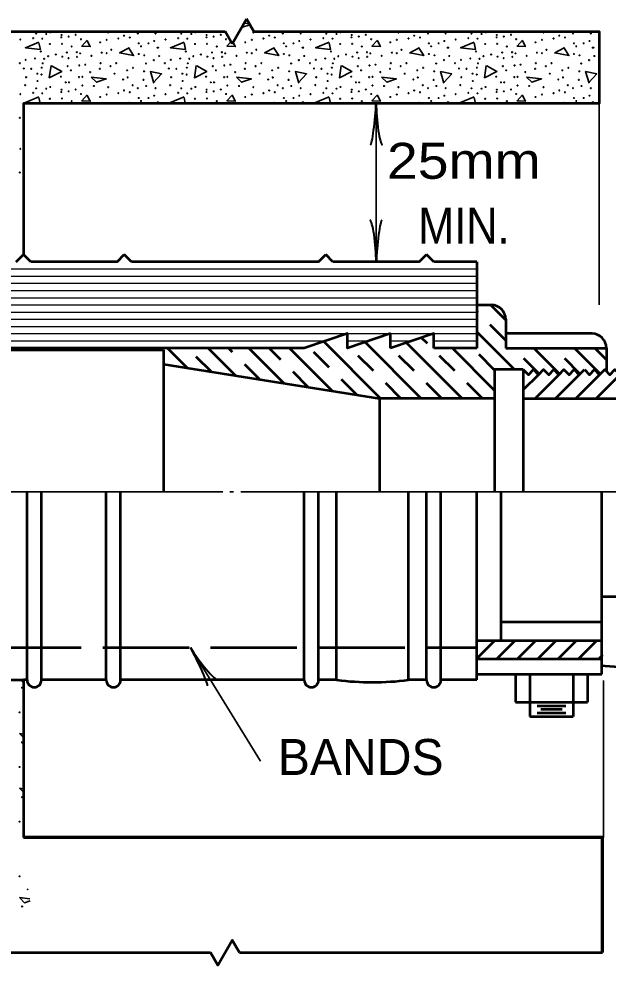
# Model space of a CAD drawing. Extents: x -50 to 806, y -9 to 535.
# Drawn here: x 191.8 to 241, y 352.2 to 431.1 of the extents above; entities that cross this region are included whole.
import ezdxf
from ezdxf.enums import TextEntityAlignment as Align

# ---------------------------------------------------------------- set-up
doc = ezdxf.new("R2010")
doc.units = 0
doc.header["$LTSCALE"] = 1.2
doc.linetypes.add('LONG_DASHED', pattern=[7.5, 6, -1.5])
doc.linetypes.add('SHORT_DASHED', pattern=[2.7, 1.5, -1.2])
doc.layers.add('1', color=7, linetype='Continuous', lineweight=35)

msp = doc.modelspace()

# ---------------------------------------------------------------- linework, layer by layer
at = {"layer": '1', "lineweight": 53}
for p, q in [((209.621, 429.012), (210.821, 431.09)), ((211.421, 430.051), (210.821, 431.09)), ((183.821, 430.051), (209.021, 430.051)), ((209.621, 429.012), (209.021, 430.051)), ((191.621, 410.851), (192.221, 411.451)), ((192.821, 410.851), (192.221, 411.451)), ((200.021, 410.851), (200.621, 411.451)), ((201.221, 410.851), (200.621, 411.451)), ((216.821, 410.851), (217.421, 411.451)), ((218.021, 410.851), (217.421, 411.451)), ((225.221, 410.851), (225.821, 411.451)), ((226.421, 410.851), (225.821, 411.451)), ((200.021, 410.851), (192.821, 410.851)), ((216.821, 410.851), (201.221, 410.851)), ((225.221, 410.851), (218.021, 410.851)), ((230.021, 410.851), (226.421, 410.851)), ((230.021, 410.851), (230.021, 403.651)), ((230.021, 407.251), (231.221, 407.251)), ((232.408, 406.004), (231.164, 407.248)), ((232.421, 406.051), (232.421, 403.651)), ((222.821, 403.651), (222.821, 404.851)), ((233.17, 401.848), (230.008, 405.01)), ((239.621, 404.851), (232.421, 404.851)), ((221.994, 399.448), (217.247, 404.194)), ((225.388, 399.448), (220.693, 404.143)), ((228.782, 399.448), (224.138, 404.091)), ((215.621, 403.651), (177.221, 403.651)), ((188.956, 403.501), (203.887, 403.501)), ((203.887, 403.501), (203.887, 391.651)), ((205.886, 401.979), (204.217, 403.648)), ((209.919, 401.341), (207.611, 403.648)), ((213.951, 400.702), (211.006, 403.648)), ((217.984, 400.064), (214.4, 403.648)), ((230.021, 403.651), (226.421, 403.651)), ((231.473, 400.151), (227.976, 403.648)), ((232.421, 403.651), (240.821, 403.651)), ((236.916, 401.496), (234.764, 403.648)), ((240.31, 401.496), (238.158, 403.648)), ((240.821, 403.651), (240.821, 401.705)), ((203.887, 402.301), (221.887, 399.451)), ((233.887, 401.851), (231.487, 401.851)), ((231.487, 401.851), (231.487, 391.651)), ((233.887, 401.851), (233.887, 391.651)), ((238.554, 401.427), (238.978, 401.851)), ((235.15, 401.418), (233.889, 400.157)), ((236.847, 401.418), (234.859, 399.43)), ((238.544, 401.418), (236.556, 399.43)), ((240.241, 401.418), (238.253, 399.43)), ((241.938, 401.418), (239.95, 399.43)), ((231.487, 399.451), (221.887, 399.451)), ((221.887, 399.451), (221.887, 391.651)), ((233.887, 399.451), (269.887, 399.451)), ((192.521, 375.979), (192.521, 391.651)), ((193.721, 375.979), (193.721, 391.651)), ((199.121, 375.979), (199.121, 391.651)), ((200.321, 375.979), (200.321, 391.651)), ((215.621, 375.979), (215.621, 391.651)), ((216.821, 375.979), (216.821, 391.651)), ((218.321, 375.979), (218.321, 391.651)), ((224.321, 375.979), (224.321, 391.651)), ((225.821, 375.979), (225.821, 391.651)), ((227.021, 375.979), (227.021, 391.651)), ((230.021, 375.979), (230.021, 391.651)), ((232.043, 379.241), (232.043, 391.651)), ((240.443, 379.592), (240.443, 391.651)), ((240.521, 382.951), (267.521, 382.951)), ((240.443, 380.803), (232.043, 380.803)), ((240.443, 376.478), (240.443, 379.592)), ((229.999, 377.741), (231.499, 379.241)), ((240.521, 379.241), (230.021, 379.241)), ((231.696, 377.741), (233.196, 379.241)), ((233.393, 377.741), (234.893, 379.241)), ((235.09, 377.741), (236.59, 379.241)), ((236.787, 377.741), (238.287, 379.241)), ((238.485, 377.741), (239.985, 379.241)), ((240.181, 377.741), (240.521, 378.081)), ((230.021, 377.741), (240.521, 377.741)), ((230.021, 376.478), (240.443, 376.478)), ((233.243, 376.533), (233.243, 374.133)), ((234.443, 376.533), (234.443, 372.933)), ((238.043, 376.533), (238.043, 372.933)), ((239.243, 376.533), (239.243, 374.133)), ((192.521, 375.979), (192.221, 375.979)), ((199.121, 375.979), (193.721, 375.979)), ((215.621, 375.979), (200.321, 375.979)), ((218.321, 375.979), (216.821, 375.979)), ((225.821, 375.979), (224.321, 375.979)), ((230.021, 375.979), (227.021, 375.979)), ((233.243, 374.133), (239.243, 374.133)), ((235.043, 373.833), (237.443, 373.833)), ((235.043, 373.233), (237.443, 373.233)), ((235.343, 373.533), (237.143, 373.533)), ((234.443, 372.933), (238.043, 372.933)), ((168.221, 353.251), (207.821, 353.251)), ((210.221, 353.251), (240.491, 353.251))]:
    msp.add_line(p, q, dxfattribs=at)
at = {"layer": '1'}
for p, q in [((210.609, 430.724), (211.063, 430.672)), ((193.612, 424.051), (193.507, 424.534)), ((205.708, 424.051), (205.603, 424.534)), ((217.804, 424.051), (217.699, 424.534)), ((229.9, 424.051), (229.795, 424.534)), ((201.019, 424.126), (200.882, 424.051)), ((201.034, 424.051), (200.971, 424.15)), ((213.115, 424.126), (212.978, 424.051)), ((213.13, 424.051), (213.067, 424.15)), ((221.621, 410.851), (221.621, 424.051)), ((225.211, 424.126), (225.074, 424.051)), ((225.226, 424.051), (225.163, 424.15)), ((237.307, 424.126), (237.17, 424.051)), ((237.322, 424.051), (237.259, 424.15)), ((240.221, 424.051), (240.221, 407.251)), ((170.506, 391.651), (208.831, 391.651)), ((209.431, 391.651), (209.731, 391.651)), ((210.331, 391.651), (218.321, 391.651)), ((206.139, 378.679), (211.986, 369.209)), ((192.221, 375.738), (191.98, 375.979)), ((240.569, 362.851), (240.569, 375.932)), ((191.885, 371.515), (192.221, 371.476)), ((192.221, 371.178), (191.885, 371.515)), ((191.885, 366.955), (192.221, 366.916)), ((192.221, 366.618), (191.885, 366.955)), ((191.885, 357.835), (192.752, 357.735))]:
    msp.add_line(p, q, dxfattribs=at)
at = {"layer": '1', "lineweight": 25}
for p, q in [((162.821, 410.251), (230.021, 410.251)), ((162.821, 409.651), (230.021, 409.651)), ((162.821, 409.051), (230.021, 409.051)), ((162.821, 408.451), (230.021, 408.451)), ((162.821, 407.851), (230.021, 407.851)), ((162.821, 407.251), (230.021, 407.251)), ((162.821, 406.651), (230.021, 406.651)), ((162.821, 406.051), (230.021, 406.051)), ((162.821, 405.451), (230.021, 405.451)), ((162.821, 404.851), (230.021, 404.851)), ((175.421, 404.251), (217.421, 404.251)), ((219.221, 404.251), (221.021, 404.251)), ((222.821, 404.251), (224.621, 404.251)), ((226.421, 404.251), (230.021, 404.251))]:
    msp.add_line(p, q, dxfattribs=at)
at = {"layer": '1', "linetype": 'SHORT_DASHED', "lineweight": 53}
for p, q in [((232.408, 404.307), (230.008, 406.707)), ((230.479, 399.448), (225.411, 404.516)), ((207.902, 401.66), (205.914, 403.648)), ((211.935, 401.021), (209.308, 403.648)), ((215.967, 400.383), (212.703, 403.648)), ((220, 399.744), (215.974, 403.77)), ((223.691, 399.448), (219.42, 403.719)), ((227.085, 399.448), (222.865, 403.667)), ((231.473, 401.848), (229.673, 403.648)), ((235.219, 401.496), (233.067, 403.648)), ((238.613, 401.496), (236.461, 403.648)), ((240.808, 402.695), (239.855, 403.648))]:
    msp.add_line(p, q, dxfattribs=at)
at = {"layer": '1', "linetype": 'LONG_DASHED', "lineweight": 53}
msp.add_line((162.821, 378.679), (230.021, 378.679), dxfattribs=at)
at = {"layer": '1', "lineweight": 70}
for p, q in [((240.491, 362.851), (192.221, 362.851)), ((240.491, 353.251), (240.491, 362.851))]:
    msp.add_line(p, q, dxfattribs=at)
at = {"layer": '1', "lineweight": 53}
for points in [[(211.421, 430.051), (240.221, 430.051), (240.221, 424.051), (192.221, 424.051), (192.221, 411.451)], [(222.821, 404.851), (219.221, 403.651), (219.221, 404.851), (215.621, 403.651)], [(226.421, 403.651), (226.421, 404.851), (222.821, 403.651)], [(233.887, 401.851), (234.311, 401.427), (234.735, 401.851), (235.159, 401.427), (235.584, 401.851), (236.008, 401.427), (236.432, 401.851), (236.857, 401.427), (237.281, 401.851), (237.705, 401.427), (238.13, 401.851), (238.554, 401.427)], [(238.978, 401.851), (239.402, 401.427), (239.827, 401.851), (240.251, 401.427), (240.675, 401.851), (241.1, 401.427), (241.524, 401.851), (241.948, 401.427), (242.373, 401.851), (242.797, 401.427), (243.221, 401.851)], [(179.064, 375.979), (192.221, 375.979), (192.221, 362.851)], [(207.821, 353.251), (208.421, 352.212), (209.621, 354.29), (210.221, 353.251)]]:
    msp.add_lwpolyline(points, dxfattribs=at)
at = {"layer": '1'}
for points in [[(211.098, 430.611), (210.403, 430.365), (210.403, 430.366)], [(193.507, 429.142), (192.379, 428.686), (193.627, 428.542), (193.507, 429.094)], [(197.539, 429.31), (197.083, 428.829), (197.779, 428.781), (197.539, 429.262)], [(205.603, 429.142), (204.475, 428.686), (205.723, 428.542), (205.603, 429.094)], [(209.519, 429.188), (209.179, 428.829), (209.875, 428.781), (209.695, 429.14)], [(217.699, 429.142), (216.571, 428.686), (217.819, 428.542), (217.699, 429.094)], [(221.731, 429.31), (221.275, 428.829), (221.971, 428.781), (221.731, 429.262)], [(229.795, 429.142), (228.667, 428.686), (229.915, 428.542), (229.795, 429.094)], [(233.827, 429.31), (233.371, 428.829), (234.067, 428.781), (233.827, 429.262)], [(201.019, 428.686), (200.227, 428.254), (201.403, 428.038), (200.971, 428.71)], [(213.115, 428.686), (212.323, 428.254), (213.499, 428.038), (213.067, 428.71)], [(225.211, 428.686), (224.419, 428.254), (225.595, 428.038), (225.163, 428.71)], [(237.307, 428.686), (236.515, 428.254), (237.691, 428.038), (237.259, 428.71)], [(194.563, 427.174), (195.403, 426.694), (194.371, 426.19), (194.515, 427.198)], [(206.659, 427.174), (207.499, 426.694), (206.467, 426.19), (206.611, 427.198)], [(218.755, 427.174), (219.595, 426.694), (218.563, 426.19), (218.707, 427.198)], [(230.851, 427.174), (231.691, 426.694), (230.659, 426.19), (230.803, 427.198)], [(203.083, 425.733), (202.795, 426.694), (203.731, 426.502), (203.059, 425.781)], [(215.179, 425.733), (214.891, 426.694), (215.827, 426.502), (215.155, 425.781)], [(227.275, 425.733), (226.987, 426.694), (227.923, 426.502), (227.251, 425.781)], [(239.371, 425.733), (239.083, 426.694), (240.019, 426.502), (239.347, 425.781)], [(193.507, 424.582), (192.379, 424.126), (193.025, 424.051)], [(197.539, 424.75), (197.083, 424.269), (197.779, 424.222), (197.539, 424.702)], [(205.603, 424.582), (204.475, 424.126), (205.121, 424.051)], [(209.635, 424.75), (209.179, 424.269), (209.875, 424.222), (209.635, 424.702)], [(217.699, 424.582), (216.571, 424.126), (217.216, 424.051)], [(221.731, 424.75), (221.275, 424.269), (221.971, 424.222), (221.731, 424.702)], [(229.795, 424.582), (228.667, 424.126), (229.312, 424.051)], [(233.827, 424.75), (233.371, 424.269), (234.067, 424.222), (233.827, 424.702)], [(218.321, 391.651), (233.887, 391.651), (240.521, 391.651), (250.121, 391.651)], [(192.769, 357.562), (192.317, 357.403), (191.885, 357.835)]]:
    msp.add_lwpolyline(points, dxfattribs=at)
for points in [[(197.875, 426.238), (199.123, 426.094), (198.307, 425.805)], [(209.971, 426.238), (211.219, 426.094), (210.403, 425.805)], [(222.067, 426.238), (223.315, 426.094), (222.499, 425.805)], [(234.163, 426.238), (235.411, 426.094), (234.595, 425.805)]]:
    msp.add_lwpolyline(points, close=True, dxfattribs=at)
for centre in [(193.279, 429.866), (194.456, 429.977), (199.284, 429.961), (201.749, 429.881), (203.228, 429.881), (205.375, 429.866), (206.552, 429.977), (211.38, 429.961), (213.845, 429.881), (215.324, 429.881), (217.471, 429.866), (218.648, 429.977), (223.476, 429.961), (225.941, 429.881), (227.42, 429.881), (229.567, 429.866), (230.744, 429.977), (235.572, 429.961), (238.037, 429.881), (239.516, 429.881), (191.959, 429.378), (193.024, 429.49), (193.788, 429.442), (194.122, 429.834), (195.378, 429.553), (195.394, 429.754), (195.982, 429.617), (196.571, 429.77), (197.01, 429.394), (198.616, 429.14), (199.157, 429.346), (200.127, 429.458), (200.604, 429.691), (201.081, 429.537), (203.117, 429.251), (204.055, 429.378), (205.12, 429.49), (205.884, 429.442), (206.218, 429.834), (207.474, 429.553), (207.49, 429.754), (208.078, 429.617), (208.667, 429.77), (209.106, 429.394), (210.712, 429.14), (211.253, 429.346), (212.223, 429.458), (212.7, 429.691), (213.177, 429.537), (215.213, 429.251), (216.151, 429.378), (217.216, 429.49), (217.98, 429.442), (218.314, 429.834), (219.57, 429.553), (219.586, 429.754), (220.174, 429.617), (220.763, 429.77), (221.202, 429.394), (222.808, 429.14), (223.349, 429.346), (224.319, 429.458), (224.796, 429.691), (225.273, 429.537), (227.309, 429.251), (228.247, 429.378), (229.312, 429.49), (230.076, 429.442), (230.41, 429.834), (231.666, 429.553), (231.682, 429.754), (232.27, 429.617), (232.859, 429.77), (233.298, 429.394), (234.904, 429.14), (235.445, 429.346), (236.415, 429.458), (236.892, 429.691), (237.369, 429.537), (239.405, 429.251), (193.661, 428.376), (194.424, 428.996), (195.426, 429.012), (195.839, 428.296), (196.237, 428.79), (196.666, 428.312), (198.743, 428.28), (199.538, 428.519), (201.828, 429.06), (202.019, 428.805), (202.639, 429.06), (203.387, 428.694), (203.451, 428.694), (205.757, 428.376), (206.52, 428.996), (207.522, 429.012), (207.935, 428.296), (208.333, 428.79), (208.762, 428.312), (210.839, 428.28), (211.634, 428.519), (213.924, 429.06), (214.115, 428.805), (214.735, 429.06), (215.483, 428.694), (215.547, 428.694), (217.853, 428.376), (218.616, 428.996), (219.618, 429.012), (220.031, 428.296), (220.429, 428.79), (220.858, 428.312), (222.935, 428.28), (223.73, 428.519), (226.02, 429.06), (226.211, 428.805), (226.831, 429.06), (227.579, 428.694), (227.643, 428.694), (229.949, 428.376), (230.712, 428.996), (231.714, 429.012), (232.127, 428.296), (232.525, 428.79), (232.954, 428.312), (235.031, 428.28), (235.826, 428.519), (238.116, 429.06), (238.307, 428.805), (238.927, 429.06), (239.675, 428.694), (239.739, 428.694), (192.404, 427.676), (193.183, 427.787), (193.947, 427.771), (194.281, 427.978), (194.917, 428.121), (195.458, 427.946), (195.967, 427.819), (196.682, 427.93), (196.946, 428.217), (197.884, 428.01), (199.157, 428.233), (201.828, 428.169), (202.29, 428.058), (203.085, 427.66), (203.53, 427.994), (204.5, 427.676), (205.279, 427.787), (206.043, 427.771), (206.377, 427.978), (207.013, 428.121), (207.554, 427.946), (208.063, 427.819), (208.778, 427.93), (209.042, 428.217), (209.98, 428.01), (211.253, 428.233), (213.924, 428.169), (214.386, 428.058), (215.181, 427.66), (215.626, 427.994), (216.596, 427.676), (217.375, 427.787), (218.139, 427.771), (218.473, 427.978), (219.109, 428.121), (219.65, 427.946), (220.159, 427.819), (220.874, 427.93), (221.138, 428.217), (222.076, 428.01), (223.349, 428.233), (226.02, 428.169), (226.482, 428.058), (227.277, 427.66), (227.722, 427.994), (228.692, 427.676), (229.471, 427.787), (230.235, 427.771), (230.569, 427.978), (231.205, 428.121), (231.746, 427.946), (232.255, 427.819), (232.97, 427.93), (233.234, 428.217), (234.172, 428.01), (235.445, 428.233), (238.116, 428.169), (238.578, 428.058), (239.373, 427.66), (239.818, 427.994), (191.911, 427.405), (192.245, 426.96), (192.865, 426.928), (193.74, 427.024), (193.82, 427.39), (195.903, 427.151), (196.173, 426.801), (196.873, 427.215), (197.375, 427.278), (198.584, 426.928), (198.648, 427.405), (199.475, 427.151), (199.952, 427.405), (200.858, 426.801), (201.351, 427.008), (202.274, 426.721), (202.433, 427.374), (204.007, 427.405), (204.341, 426.96), (204.961, 426.928), (205.836, 427.024), (205.916, 427.39), (207.999, 427.151), (208.269, 426.801), (208.969, 427.215), (209.471, 427.278), (210.68, 426.928), (210.744, 427.405), (211.571, 427.151), (212.048, 427.405), (212.954, 426.801), (213.447, 427.008), (214.37, 426.721), (214.529, 427.374), (216.103, 427.405), (216.437, 426.96), (217.057, 426.928), (217.932, 427.024), (218.012, 427.39), (220.095, 427.151), (220.365, 426.801), (221.065, 427.215), (221.567, 427.278), (222.776, 426.928), (222.84, 427.405), (223.667, 427.151), (224.144, 427.405), (225.05, 426.801), (225.543, 427.008), (226.466, 426.721), (226.625, 427.374), (228.199, 427.405), (228.533, 426.96), (229.153, 426.928), (230.028, 427.024), (230.108, 427.39), (232.191, 427.151), (232.461, 426.801), (233.161, 427.215), (233.663, 427.278), (234.872, 426.928), (234.936, 427.405), (235.763, 427.151), (236.24, 427.405), (237.146, 426.801), (237.639, 427.008), (238.562, 426.721), (238.721, 427.374), (192.436, 426.228), (193.374, 426.53), (193.39, 425.91), (193.724, 426.451), (195.346, 426.276), (196.849, 426.241), (197.121, 426.26), (197.773, 426.658), (199.809, 426.53), (200.524, 426.037), (200.906, 426.212), (202.226, 426.005), (204.532, 426.228), (205.47, 426.53), (205.486, 425.91), (205.82, 426.451), (207.442, 426.276), (208.945, 426.241), (209.217, 426.26), (209.869, 426.658), (211.905, 426.53), (212.62, 426.037), (213.002, 426.212), (214.322, 426.005), (216.628, 426.228), (217.566, 426.53), (217.582, 425.91), (217.916, 426.451), (219.538, 426.276), (221.041, 426.241), (221.313, 426.26), (221.965, 426.658), (224.001, 426.53), (224.716, 426.037), (225.098, 426.212), (226.418, 426.005), (228.724, 426.228), (229.662, 426.53), (229.678, 425.91), (230.012, 426.451), (231.634, 426.276), (233.137, 426.241), (233.409, 426.26), (234.061, 426.658), (236.097, 426.53), (236.812, 426.037), (237.194, 426.212), (238.514, 426.005), (192.356, 425.576), (193.279, 425.306), (194.122, 425.274), (194.456, 425.417), (195.394, 425.194), (195.744, 425.799), (196.014, 425.799), (196.571, 425.21), (197.121, 425.544), (198.091, 425.496), (199.284, 425.401), (200.604, 425.131), (201.319, 425.56), (201.749, 425.321), (202.449, 425.496), (203.228, 425.321), (204.452, 425.576), (205.375, 425.306), (206.218, 425.274), (206.552, 425.417), (207.49, 425.194), (207.84, 425.799), (208.11, 425.799), (208.667, 425.21), (209.217, 425.544), (210.187, 425.496), (211.38, 425.401), (212.7, 425.131), (213.415, 425.56), (213.845, 425.321), (214.545, 425.496), (215.324, 425.321), (216.548, 425.576), (217.471, 425.306), (218.314, 425.274), (218.648, 425.417), (219.586, 425.194), (219.936, 425.799), (220.206, 425.799), (220.763, 425.21), (221.313, 425.544), (222.283, 425.496), (223.476, 425.401), (224.796, 425.131), (225.511, 425.56), (225.941, 425.321), (226.641, 425.496), (227.42, 425.321), (228.644, 425.576), (229.567, 425.306), (230.41, 425.274), (230.744, 425.417), (231.682, 425.194), (232.032, 425.799), (232.302, 425.799), (232.859, 425.21), (233.409, 425.544), (234.379, 425.496), (235.572, 425.401), (236.892, 425.131), (237.607, 425.56), (238.037, 425.321), (238.737, 425.496), (239.516, 425.321), (191.959, 424.818), (193.024, 424.93), (193.788, 424.882), (194.424, 424.436), (195.378, 424.993), (195.426, 424.452), (195.982, 425.057), (197.01, 424.834), (198.616, 424.58), (199.157, 424.786), (200.127, 424.898), (201.081, 424.977), (201.828, 424.5), (202.639, 424.5), (203.117, 424.691), (204.055, 424.818), (205.12, 424.93), (205.884, 424.882), (206.52, 424.436), (207.474, 424.993), (207.522, 424.452), (208.078, 425.057), (209.106, 424.834), (210.712, 424.58), (211.253, 424.786), (212.223, 424.898), (213.177, 424.977), (213.924, 424.5), (214.735, 424.5), (215.213, 424.691), (216.151, 424.818), (217.216, 424.93), (217.98, 424.882), (218.616, 424.436), (219.57, 424.993), (219.618, 424.452), (220.174, 425.057), (221.202, 424.834), (222.808, 424.58), (223.349, 424.786), (224.319, 424.898), (225.273, 424.977), (226.02, 424.5), (226.831, 424.5), (227.309, 424.691), (228.247, 424.818), (229.312, 424.93), (230.076, 424.882), (230.712, 424.436), (231.666, 424.993), (231.714, 424.452), (232.27, 425.057), (233.298, 424.834), (234.904, 424.58), (235.445, 424.786), (236.415, 424.898), (237.369, 424.977), (238.116, 424.5), (238.927, 424.5), (239.405, 424.691), (196.237, 424.23), (202.019, 424.245), (203.387, 424.134), (203.451, 424.134), (208.333, 424.23), (214.115, 424.245), (215.483, 424.134), (215.547, 424.134), (220.429, 424.23), (226.211, 424.245), (227.579, 424.134), (227.643, 424.134), (232.525, 424.23), (238.307, 424.245), (239.675, 424.134), (239.739, 424.134), (191.911, 422.845), (191.959, 420.258), (191.911, 418.285), (192.101, 375.334), (191.894, 373.287), (192.101, 370.774), (191.894, 368.727), (192.101, 366.214), (191.894, 364.167), (191.894, 359.607), (192.101, 357.094)]:
    msp.add_circle(centre, 0.0318, dxfattribs=at)
for centre, start, end in [((198.091, 430.056), 189.85166, 350.14834), ((202.449, 430.056), 189.85166, 350.14834), ((214.545, 430.056), 189.85166, 350.14834), ((222.283, 430.056), 189.85166, 350.14834), ((226.641, 430.056), 189.85166, 350.14834), ((234.379, 430.056), 189.85166, 350.14834), ((238.737, 430.056), 189.85166, 350.14834), ((192.245, 422.4), 139.14202, 220.85798), ((192.245, 417.84), 139.14202, 220.85798), ((192.594, 358.525), 129.87991, 264.14833)]:
    msp.add_arc(centre, 0.0318, start, end, dxfattribs=at)
at = {"layer": '1', "lineweight": 53}
for centre, radius, start, end in [((231.221, 406.051), 1.2, 0, 90), ((239.621, 403.651), 1.2, 0, 90), ((193.121, 375.968), 0.6, 178.95622, 1.04378), ((199.721, 375.968), 0.6, 178.95622, 1.04378), ((216.221, 375.968), 0.6, 178.95622, 1.04378), ((221.321, 400.397), 24.602, 262.99578, 277.00423), ((226.421, 375.968), 0.6, 178.95622, 1.04378)]:
    msp.add_arc(centre, radius, start, end, dxfattribs=at)
at = {"layer": '1', "lineweight": 40}
for centre, major_axis, ratio, start_param, end_param in [((221.367, 422.706), (0.211, 2.108), 0.07063, 3.140715, 5.41811), ((221.367, 422.706), (0.211, 2.108), 0.07063, 3.140715, 5.41811), ((221.953, 422.742), (-0.187, 2.143), 0.122415, 0.896353, 3.141593), ((221.953, 422.742), (-0.187, 2.143), 0.122415, 0.896353, 3.141593), ((221.29, 412.16), (0.187, -2.143), 0.122415, 0.896353, 3.141593), ((221.875, 412.196), (-0.211, -2.108), 0.07063, 3.140715, 5.41811), ((206.629, 377.402), (0.928, -1.904), 0.07063, 6.282307, 8.559703), ((207.109, 377.739), (-1.285, 1.725), 0.122415, 0.896353, 3.141593)]:
    msp.add_ellipse(centre, major_axis=major_axis, ratio=ratio, start_param=start_param, end_param=end_param, dxfattribs=at)
at = {"layer": '1', "lineweight": 53}
msp.add_spline([(240.336, 377.179), (243.297, 376.633), (245.712, 373.516), (244.232, 369.462), (243.686, 365.877), (245.712, 365.487), (247.27, 366.734), (248.907, 369.307), (250.309, 370.398), (251.946, 369.229), (250.309, 366.968), (249.92, 365.253), (250.076, 363.772), (251.79, 363.305), (254.829, 365.175), (257.088, 368.293), (260.906, 370.086), (267.374, 371.099), (273.521, 370.351)], degree=3, dxfattribs=at)

# ---------------------------------------------------------------- texts
at = {"layer": '1'}
for s, width, p in [('25mm', 1.15, (228.934, 417.76)), ('MIN.', 0.9, (228.934, 412.36))]:
    msp.add_text(s, height=3, dxfattribs=dict(at, width=width)).set_placement(p, align=Align.CENTER)
msp.add_text('BANDS', height=3, dxfattribs=at).set_placement((213.423, 368.059))

doc.saveas('drawing.dxf')
